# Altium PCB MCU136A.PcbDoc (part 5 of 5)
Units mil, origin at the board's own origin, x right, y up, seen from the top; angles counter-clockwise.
Board outline 3937.01 x 4724.41 mil, 4 copper layers (Top Layer, Signal Layer 1, Signal Layer 2, Bottom Layer), stack 60 mil thick; 390 components, 224 nets, 1130 pads, 1344 vias.
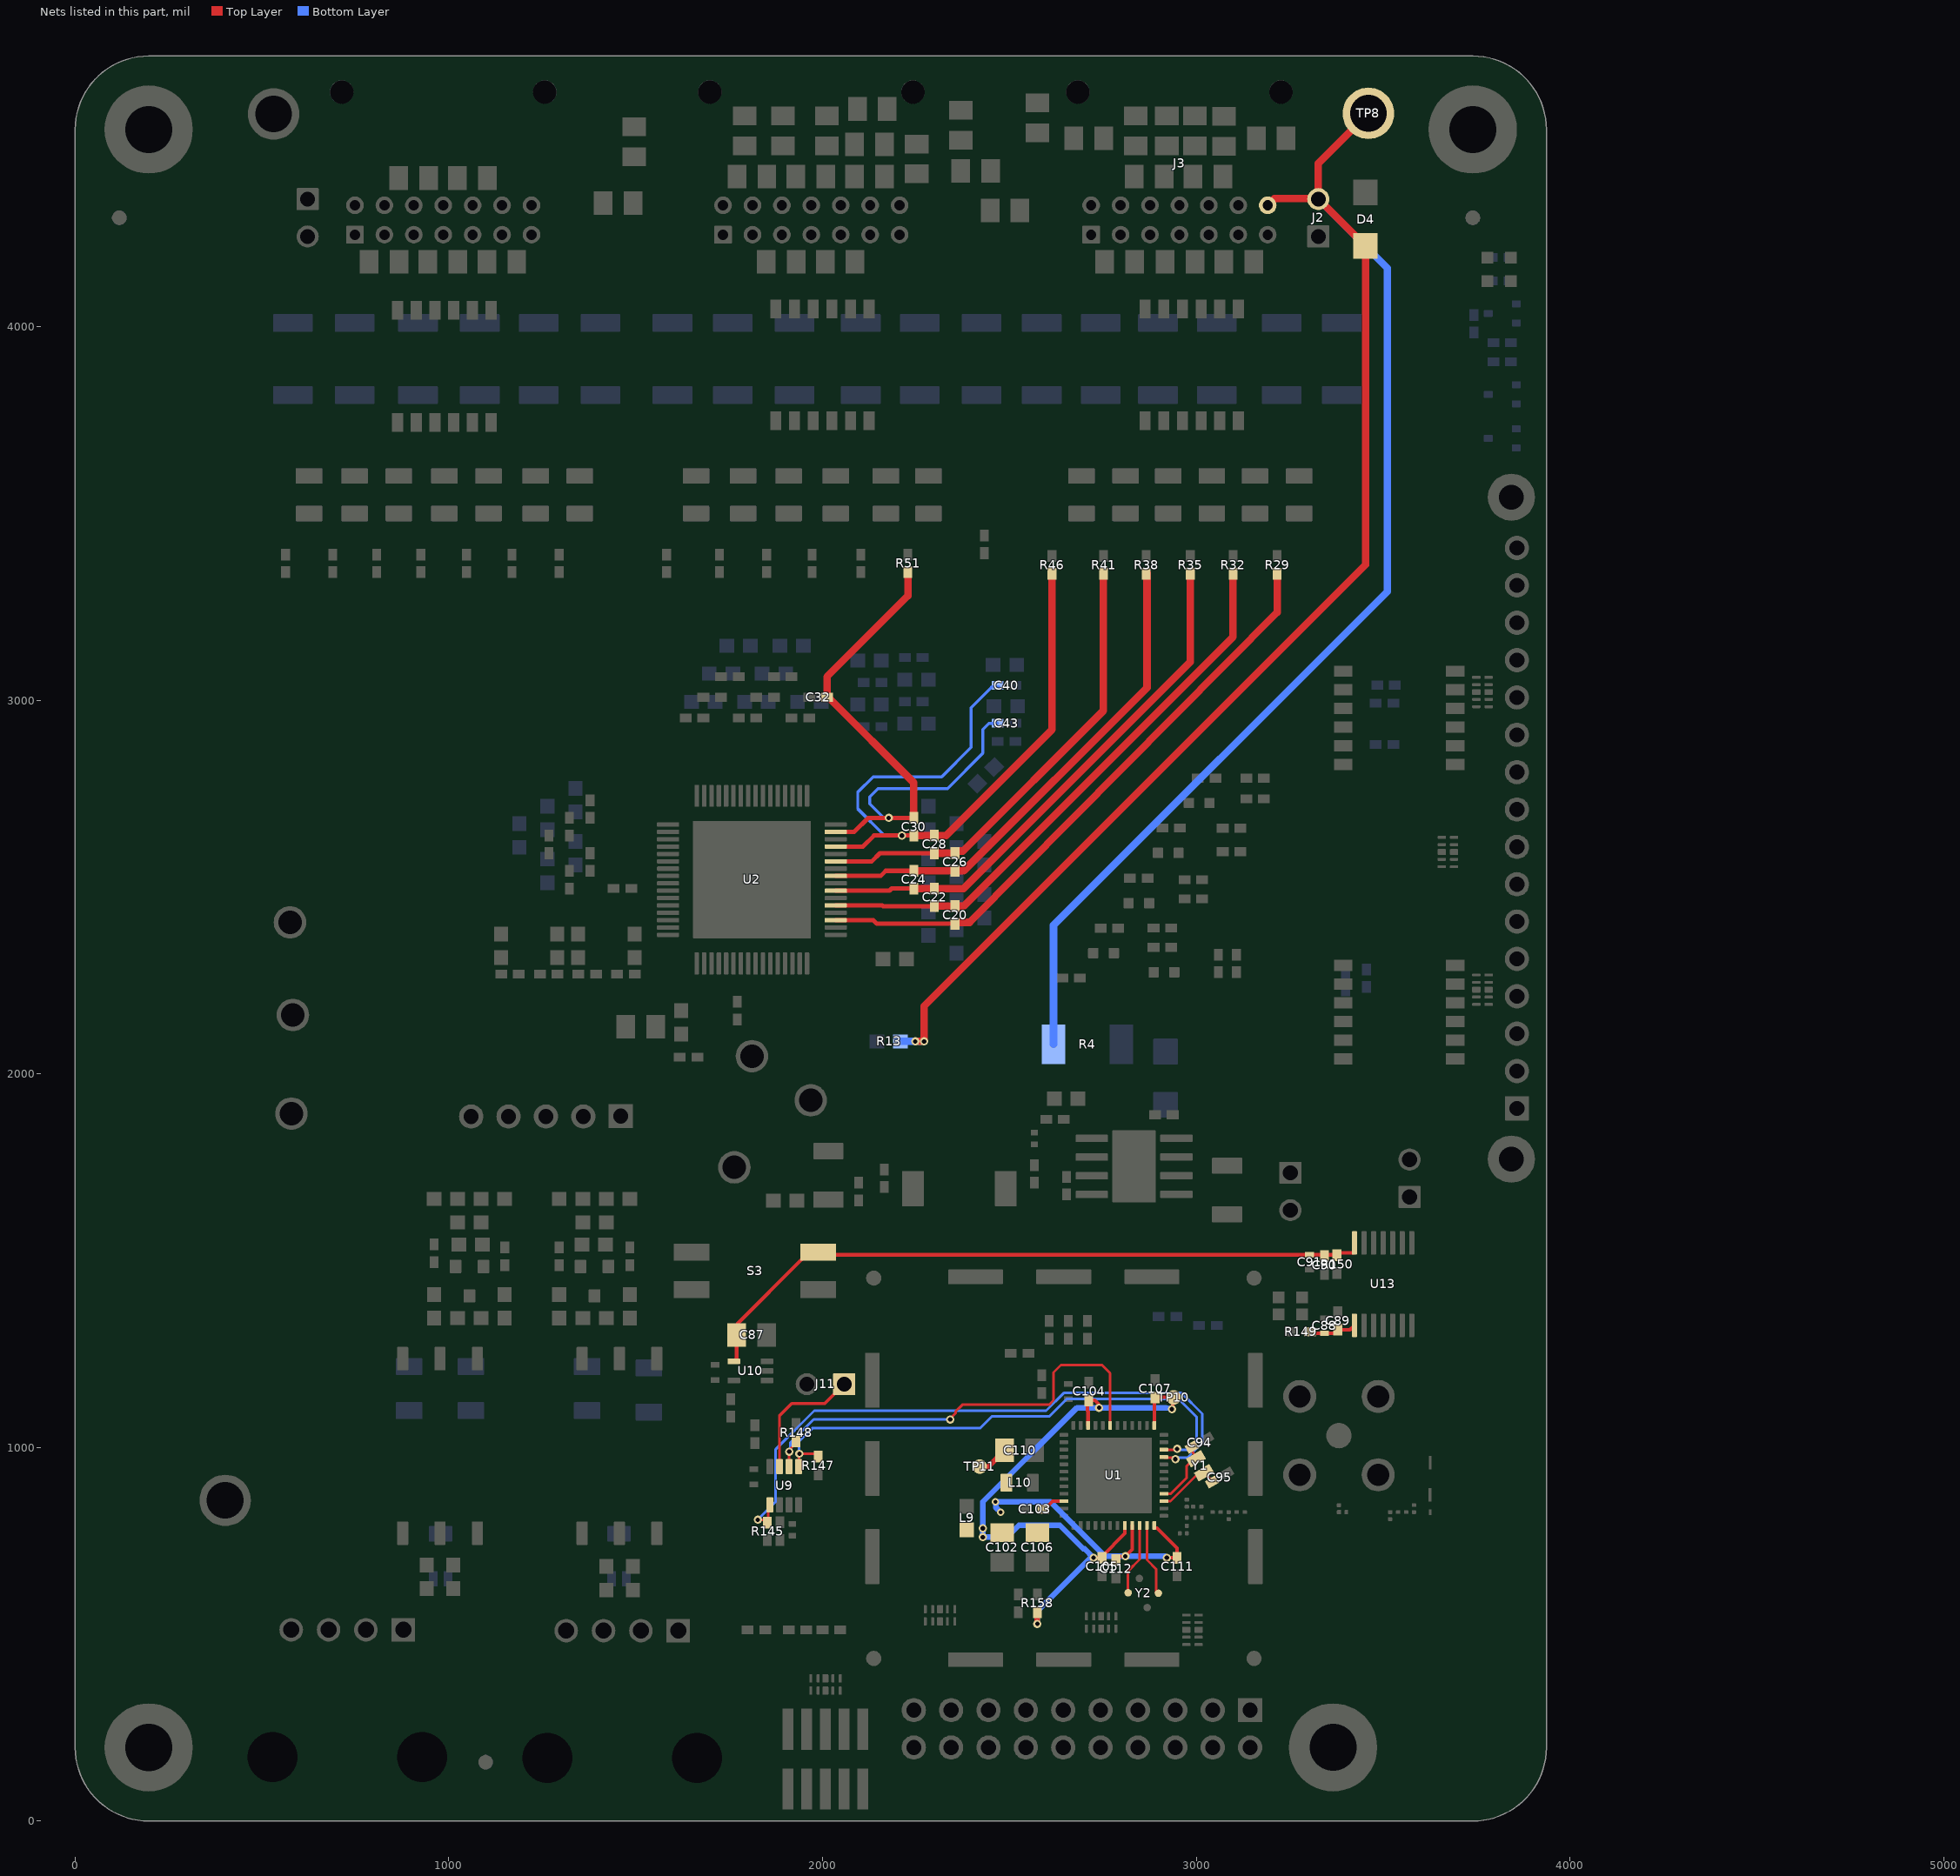
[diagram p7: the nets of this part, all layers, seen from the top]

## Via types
v1: diameter 22, hole 12, Top Layer to Bottom Layer, tented both sides, 890 vias
v2: diameter 22.01, hole 12.01, Top Layer to Bottom Layer, tented both sides, 402 vias
v3: diameter 19.68, hole 7.87, Top Layer to Bottom Layer, tented both sides, 21 vias
v4: diameter 24, hole 8, Top Layer to Bottom Layer, tented both sides, 12 vias
v5: diameter 20, hole 10, Top Layer to Bottom Layer, tented both sides, 7 vias
v6: diameter 24.8, hole 12.99, Top Layer to Bottom Layer, tented bottom, 6 vias
v7: diameter 17.46, hole 7.87, Top Layer to Bottom Layer, tented both sides, 6 vias

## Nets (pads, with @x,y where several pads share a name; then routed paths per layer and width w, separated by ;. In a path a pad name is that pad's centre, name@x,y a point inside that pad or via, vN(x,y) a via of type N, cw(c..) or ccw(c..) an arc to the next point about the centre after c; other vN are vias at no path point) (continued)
VC12: C30.2 C32.1 C43.1 R51.2 U2.15 | length 1616.1
  Top Layer w11.81: U2.15@2035.43,2647.64 2084.65,2647.64 2122.05,2685.04 v2(2177.17,2685.04) C30.2@2244.09,2685.04
  Top Layer w20: R51.2@2228.35,3342.52 2228.35,3279.53 2011.81,3062.99 C32.1@2011.81,3007.87 2013.62,3006.06 2017.56,3006.06 2244.09,2779.53 C30.2@2244.09,2685.04
  Bottom Layer w8: v2(2177.17,2685.04) 2163.55,2685.04 2125.98,2722.6 2125.98,2741.06 2148.7,2763.78 2334.65,2763.78 2429.13,2858.27 2429.13,2921.26 2445.44,2937.57 2467.9,2937.57 C43.1@2468.5,2938.17
VC13: C28.2 C30.1 C40.1 R46.2 U2.13 | length 1875.5
  Top Layer w11.81: U2.13@2035.43,2608.27 2108.27,2608.27 2137.8,2637.8 v2(2212.6,2637.8) C30.1@2240.16,2637.8
  Top Layer w20: C30.1@2244.09,2637.8 C28.2@2299.21,2637.8 2330.71,2637.8 2614.17,2921.26 R46.2@2614.17,3338.58 R46.2@2614.17,3342.52
  Bottom Layer w8: v2(2212.6,2637.8) 2165.81,2637.8 2094.33,2709.27 2094.33,2754.39 2135.21,2795.28 2318.9,2795.28 2397.64,2874.02 2397.64,2980.31 2448.53,3031.2 2452.76,3035.43 C40.1@2472.44,3035.43
VC14: C26.2 C28.1 R41.2 U2.11 | length 1248.2
  Top Layer w11.81: U2.11@2035.43,2568.9 2131.89,2568.9 2153.54,2590.55 C28.1@2299.21,2590.55
  Top Layer w20: C28.1@2299.21,2590.55 C26.2@2354.33,2590.55 2354.33,2594.49 2356.14,2596.3 2375.83,2596.3 2751.43,2971.9 2751.43,3334.1 R41.2@2751.97,3334.65
VC15: C24.2 C26.1 R38.2 U2.9 | length 1351.5
  Top Layer w11.81: U2.9@2035.43,2529.53 2155.51,2529.53 2169.29,2543.31 C24.2@2244.09,2543.31
  Top Layer w20: C24.2@2244.09,2543.31 C26.1@2354.33,2543.31 2377.95,2543.31 2868.32,3033.67 2868.32,3340.34 R38.2@2866.14,3342.52
VC16: C22.2 C24.1 R35.2 U2.7 | length 1438.6
  Top Layer w11.81: U2.7@2035.43,2490.16 2179.13,2490.16 2185.04,2496.06 C24.1@2244.09,2496.06
  Top Layer w20: C24.1@2244.09,2496.06 C22.2@2299.21,2496.06 2377.95,2496.06 2984.25,3102.36 R35.2@2984.25,3338.58
VC17: C20.2 C22.1 R32.2 U2.5 | length 1537.1
  Top Layer w11.81: U2.5@2035.43,2450.79 2159.45,2450.79 2161.42,2448.82 C22.1@2299.21,2448.82 ; R32.2@3098.43,3338.58 R32.2@3102.36,3342.52
  Top Layer w20: C22.1@2299.21,2448.82 2377.95,2448.82 3098.43,3169.29 R32.2@3098.43,3338.58
VC18: C20.1 R29.2 U2.3 | length 1634.2
  Top Layer w11.81: U2.3@2035.43,2411.42 2135.83,2411.42 2145.67,2401.57 C20.1@2354.33,2401.57
  Top Layer w20: C20.1@2354.33,2405.51 2393.7,2405.51 3216.54,3235.27 R29.2@3216.54,3338.58
VCCA: C88.1 C89.1 R149.1 U13.1 | length 129.9
  Top Layer w10: R149.1@3303.81,1309.42 3307.78,1305.45 3346.05,1305.45 3376.32,1305.45 3385.83,1314.96 3411.42,1314.96 U13.1@3423.23,1326.77
VDDR: C110.1 C111.1 C112.1 L10.2 TP11.1 U1.45 U1.48 | length 889.6
  Top Layer w9.45: C112.1@2785.28,698.72 2795.13,708.58 v2(2810.52,708.58) 2828.74,726.8 U1.45@2828.74,791.34 ; U1.48@2887.8,791.34 2887.8,784.45 2887.99,784.25 2894.88,784.25 2948.82,730.32 C111.1@2948.82,712.6 ; v2(2921.26,704.72) C111.1@2948.82,704.72
  Top Layer w15: TP11.1@2425.53,948.48 2443.91,948.48 C110.1@2487.56,992.13
  Bottom Layer w15: v5(2476.38,826.77) 2463.45,839.7 2463.45,853.5 v5(2462.49,854.45) 2610,854.45 2755.87,708.58 v2(2810.52,708.58) 2915.51,708.58 2919.36,704.72 v2(2921.26,704.72)
VDDS: C102.1 C103.1 C104.1 C105.1 C106.1 C107.1 L9.2 R158.2 TP10.1 U1.13 U1.22 U1.34 U1.44 | length 1769.7
  Top Layer w9.45: C103.1@2602.36,842.52 2616.14,856.3 U1.34@2645.67,856.3 ; U1.22@2710.63,1059.06 2710.63,1096.46 2708.66,1098.43 2708.66,1125.98 2729.11,1125.98 2737.75,1117.34 2737.75,1108.7 v2(2740.16,1106.3) ; v2(2725.23,704.57) 2747.87,704.57 C105.1@2748.03,704.72 2748.03,708.66 2809.06,769.69 U1.44@2809.06,791.34 ; U1.13@2887.8,1059.06 2887.8,1124.02 C107.1@2889.76,1125.98 ; C107.1@2889.73,1133.57 2890.02,1133.86 TP10.1@2939.4,1133.86 2937.19,1131.65 2937.19,1107.75 v1@2939.4,1105.54
  Top Layer w15: v1(2574.8,527.56) R158.2@2574.8,559.06
  Bottom Layer w15: v1(2574.8,527.56) 2574.8,562.21 2717.16,704.57 v2(2725.23,704.57) 2701.04,728.75 2697.65,728.75 2635.06,791.34 2525.76,791.34 2494.27,759.84 v2(2429.13,759.84) v2(2429.13,783.46) 2429.13,854.33 2681.1,1106.3 v2(2740.16,1106.3) 2919.37,1106.3 v1(2934.98,1102.5)
VPWR: D4.1 J2.2 J3.14 R4.2 R13.1 TP8.1 | length 6020.4
  Top Layer w19.68: v2(2248.03,2086.61) v2(2271.65,2086.61) 2271.65,2181.1 3452.76,3362.2 D4.1@3452.76,4215.94
  Top Layer w20: J3.14@3191.22,4324.8 3208.94,4342.52 J2.2@3326.77,4342.52 ; D4.1@3452.76,4215.94 3327.36,4341.34 J2.2@3326.77,4341.34 J2.2@3326.77,4342.52 ; TP8.1@3460.63,4570.87 3326.77,4437.01 J2.2@3326.77,4342.52
  Bottom Layer w19.68: R13.1@2208.66,2086.61 v2(2248.03,2086.61) v2(2271.65,2086.61)
  Bottom Layer w20: R4.2@2618.11,2078.74 2618.11,2397.64 3511.81,3291.34 3511.81,4156.3 J2.2@3326.77,4341.34
WD_SET0: R145.1 U1.9 U9.1 | length 1706.1
  Top Layer w7: v1(1826.99,806.49) 1847.06,806.49 R145.1@1854.33,799.21 ; R145.1@1854.33,807.09 U9.1@1854.33,841.54 ; U1.9@2913.39,974.41 2914.81,972.99 2935.61,972.99 2940.16,968.44 v1(2944.22,968.44)
  Bottom Layer w7: v1(1826.99,806.49) 1826.99,807.3 1874.84,855.15 1874.84,995.24 1978.02,1098.43 2598.43,1098.43 2645.67,1145.67 2960.63,1145.67 3016.08,1090.22 3016.08,1012.14 2976.38,972.44 2948.82,972.44 v1@2940.94,964.57
WD_SET1: R147.2 U1.10 U9.5 | length 1414.5
  Top Layer w7: U9.5@1936.02,948.82 1937.14,949.94 1937.14,981.88 v1(1938.26,983) 1986.94,983 R147.2@1989.62,980.32 ; U1.10@2913.39,994.09 v1@2946.73,994.09
  Bottom Layer w7: v1(1938.26,983) 1937.01,984.25 1937.01,1015.75 1972.44,1051.18 2421.26,1051.18 2452.76,1082.68 2606.3,1082.68 2653.54,1129.92 2952.76,1129.92 3001.28,1081.4 3001.28,1015.73 2978.75,993.19 2951.69,993.19 v1(2948.82,996.06)
WDI_CC: R148.2 U1.19 U9.6 | length 1232.3
  Top Layer w7: U9.6@1911.91,950.3 1910.64,951.56 1910.64,988.51 1913.72,991.59 1913.72,996.4 R148.2@1929.13,1011.81 ; v1(2341.78,1074.8) 2341.78,1076.98 2355.89,1091.1 2355.89,1096.05 2374.02,1114.17 2606.3,1114.17 2618.11,1125.98 2618.11,1200.79 2637.8,1220.47 2748.03,1220.47 2769.69,1198.82 U1.19@2769.69,1059.06
  Bottom Layer w7: v1@1913.39,988.72 1913.39,1011.81 1976.38,1074.8 v1(2341.78,1074.8)
  other v1: 1910.85,988.72
WDO_T: J11.1 U9.7 | length 344
  Top Layer w8: U9.7@1884.84,948.82 1884.84,1084.86 1917.32,1117.34 2005.92,1117.34 J11.1@2057.87,1169.29
WL_PWR: C87.2 C90.1 C91.1 R150.1 S3.4 U10.4 U13.14 | length 1835.9
  Top Layer w10: U10.4@1762.8,1230.31 1770.31,1237.83 C87.2@1770.31,1300.96 ; C87.2@1771.65,1300.96 1771.65,1330.71 1945.16,1504.21 1945.16,1505.2 1955.71,1515.75 R150.1@3376.13,1515.75 ; R150.1@3376.13,1514.05 3382.83,1520.75 3421.34,1520.75 U13.14@3423.23,1522.64
X32K_Q1: C95.1 U1.3 Y1.2 | length 166.7
  Top Layer w7: U1.3@2913.39,856.3 2931.1,856.3 3001.97,927.17 3015.99,927.17 Y1.2@3020.94,932.12
  Top Layer w8: Y1.2@3020.94,932.12 3039.24,913.83 C95.1@3039.24,911.97
X32K_Q2: C94.1 U1.4 Y1.1 | length 171.4
  Top Layer w7: U1.4@2913.39,876.39 2932.35,876.39 2973.91,917.95 2973.91,949.25 2994.29,969.63 Y1.1@2999.29,969.63 2999.29,977.01 2990.87,985.42 C94.1@2990.87,994.69
X48M_N: U1.46 Y2.1 | length 192.9
  Top Layer w7: Y2.1@2817.45,611.31 2817.45,669.33 2848.43,700.31 U1.46@2848.43,791.34
X48M_P: U1.47 Y2.3 | length 191.4
  Top Layer w7: U1.47@2868.11,791.34 2868.11,698.82 2893.32,673.61 Y2.3@2893.32,610.33
pads on no net: FID1.1 FID2.1 FID3.1 FID4.1 FID5.1 FID6.1 J3. J3.1 J4. J4.1 J4.14 J5. J5.14 J7.1 J7.2 J7.MH1 J7.MH2 J9.3 J9.4 J9.MH1 J9.MH2 J10.6 J10.7 J10.8 MP1. MP2. MP3. MP4. S1.2 S1.11 S3.3 SH-J1.0 SH-J2.0 SH-J3.0 SH-J4.0 SH-J5.0 T1.5 T2.5 U1.5 U1.6 U1.7 U1.8 U1.20 U1.21 U1.28 U1.29 U1.30 U1.31 U1.32 U1.36 U1.42 U1.43 U3.3@3657.15,2593.74 U3.8@3690.03,2593.74 U4.3@3749.52,2225.2 U4.8@3782.39,2225.2 U5.3@3749.52,3022 U5.8@3782.39,3022 U8.3@2007.87,348.96 U8.5 U8.6 U8.8@2007.87,381.83 U10.1 U10.3 U11.3@2745.65,515.06 U11.8@2745.65,547.93 U12.2 U12.3@3006.44,511.81 U12.4 U12.5 U12.6 U12.7 U12.8@2973.56,511.81 U12.9 U13.3 U13.6 U13.9 U13.12 U14.3@2314.5,534.18 U14.8@2314.5,567.06

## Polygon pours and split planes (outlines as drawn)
GND on Signal Layer 1 "SIGNAL_LAYER_1_GND_P092" (solid, pour order 92): 0,4724.41 3937.01,4724.41 3937.01,0 0,0
GND on Signal Layer 2 "SIGNAL_LAYER_2_GND_P093" (solid, pour order 93): 0,4724.41 3937.01,4724.41 3937.01,0 0,0
GND on Bottom Layer "BOTTOM_LAYER_GND_P096" (solid, remove dead copper, pour order 96): 3937.01,0 0,0 0,4724.41 3937.01,4724.41
GND on Top Layer "TOP_LAYER_GND_P094" (solid, remove dead copper, pour order 94): 3937.01,0 0,0 0,4724.41 3937.01,4724.41

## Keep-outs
Keep-Out Layer:
  text ".Layer_Name" at 446,-854.48 h60

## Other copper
Top Layer:
  pour cut-out: 3342.52,1070.87 cw(c3381.89,1031.5) 3421.26,1070.87 cw(c3381.89,1031.5) 3421.26,992.13 cw(c3381.89,1031.5) 3342.52,992.13 cw(c3381.89,1031.5)
  pour cut-out: 2078.44,305.8 2087.31,305.8 2087.31,184.68 2078.44,184.68 2078.44,305.79
  pour cut-out: 1928.44,302.64 1937.31,302.64 1937.31,184.68 1928.44,184.68
  pour cut-out: 2803.09,676.98 2806.01,674.05 2806.01,671.6 2838.74,704.32 2838.74,714.26 2835.81,714.26 2833.74,716.33 2827.52,710.12 2827.52,701.53 2817.56,691.57 2805.79,691.57 2803.09,688.87
  pour cut-out: 3662.31,3006.76 3662.31,2998.76 3709.54,2998.76 3712.93,3002.14 3712.93,3004.84 3711.01,3006.76
  region net LDO_C: 3023.62,1787.4 3023.62,1724.41 3039.37,1724.41 3043.31,1728.35 3043.31,1775.59
  pour cut-out: 2990.98,4105.27 2993.86,4105.27 2995.94,4103.2 2995.46,4102.72 2995.46,4078.73 2992.42,4078.73 2991.94,4078.25 2992.58,4077.61 2992.58,4016.38 2995.46,4016.38 2995.94,4016.86 2995.61,4017.18 2983.77,4017.18 2983.77,4078.08 2983.49,4078.36 2978.1,4078.36 2978.1,4091.11 2977.25,4091.96 2990.57,4105.27
  pour cut-out: 1987.83,4113.4 1989.01,4114.58 1993.88,4114.58 1993.88,4112.89 2008.01,4098.77 2007.51,4098.26 2007.51,4078.25 2004.31,4078.25 2003.81,4077.74 2004.14,4077.41 2004.14,4016.69 2008.52,4016.69 2008.68,4016.52 2008.13,4015.97 2008.13,3936.86 1984.99,3936.86 1984.45,3937.4 1989.35,3942.3 1989.35,4014.99 1991.26,4016.89 1991.8,4016.35 1996.43,4016.35 1996.43,4078.44 1996.11,4078.76 1995.84,4078.5 1988.21,4078.5 1988.21,4113.1 1988.05,4113.25
  pour cut-out: 2046.07,4077.95 2046.07,4016.68 2046.87,4015.88 2046.6,4015.61 2041.56,4015.61 2041.56,3929.94 2053.23,3918.27 2056.95,3918.27 2059.34,3920.66 2058.8,3921.19 2058.8,4017.21 2056.15,4017.21 2054.03,4019.33 2054.03,4077.95 2046.6,4077.95 2046.34,4077.68
  pour cut-out: 3321.28,3578.06 3321.28,3523.61 3321.02,3523.35 3316.82,3527.56 3232.28,3527.56 3232.28,3543.31 3267.72,3578.74 3321.46,3578.74
  pour cut-out: 2972.44,3645.67 2996.06,3645.67 2996.06,3582.68 2968.5,3555.12 2964.57,3555.12 2964.57,3531.5 2968.5,3527.56 2964.57,3523.62 2885.83,3523.62 2885.83,3535.43 2881.89,3539.37 2913.39,3570.87 2964.57,3570.87 2972.44,3578.74
  pour cut-out: 2657.48,3433.07 2629.92,3433.07 2629.92,3519.68 2681.1,3570.87 2736.22,3570.87 2740.16,3574.8 2740.16,3645.67 2763.78,3645.67 2763.78,3582.68 2736.22,3555.12 2736.22,3527.56 2653.54,3527.56 2645.67,3519.68 2645.67,3444.88
  pour cut-out: 2271.65,3570.87 2326.77,3570.87 2326.77,3523.62 2248.03,3523.62 2244.09,3527.56 2244.09,3543.31
  pour cut-out: 1952.76,3649.61 1992.13,3649.61 1988.19,3645.67 1988.19,3582.68 1956.69,3551.18 1956.69,3527.56 1866.14,3527.56 1866.14,3543.31 1870.08,3543.31 1897.64,3570.87 1948.82,3570.87 1956.69,3578.74 1952.76,3582.68
  pour cut-out: 1393.7,3570.87 1393.7,3527.56 1311.02,3527.56 1311.02,3543.31 1338.58,3570.87
  pour cut-out: 665.35,3657.48 708.66,3657.48 700.79,3649.61 700.79,3594.49 673.23,3566.93 673.23,3527.56 578.74,3527.56 578.74,3539.37 610.24,3570.87 665.35,3570.87 673.23,3578.74 669.29,3582.68 669.29,3653.54
  pour cut-out: 1023.62,3661.42 1070.87,3661.42 1070.87,3657.48 1059.06,3645.67 1059.06,3594.49 1031.5,3566.93 1031.5,3527.56 948.82,3527.56 948.82,3531.5 992.13,3574.8 1031.5,3574.8 1031.5,3578.74 1035.43,3582.68 1035.43,3649.61
  region net CB13: 2661.42,3440.94 2653.54,3452.76 2653.54,3519.68 2732.28,3519.68 2732.28,3452.76 2724.41,3440.94
  region net CELL13: 2724.41,3657.48 2732.28,3645.67 2732.28,3578.74 2653.54,3578.74 2653.54,3645.67 2661.42,3657.48
  region net CB18: 3244.09,3440.94 3236.22,3452.76 3236.22,3519.68 3314.96,3519.68 3314.96,3452.76 3307.09,3440.94
  region net CB17: 3125.98,3440.94 3118.11,3452.76 3118.11,3519.68 3196.85,3519.68 3196.85,3452.76 3188.98,3440.94
  region net CB16: 3010.15,3441.45 3002.27,3453.26 3002.27,3520.19 3081.01,3520.19 3081.01,3453.26 3073.14,3441.45
  region net CB15: 2893.7,3440.94 2885.83,3452.76 2885.83,3519.68 2964.57,3519.68 2964.57,3452.76 2956.69,3440.94
  region net CB14: 2779.53,3440.94 2771.65,3452.76 2771.65,3519.68 2850.39,3519.68 2850.39,3452.76 2842.52,3440.94
  region net CELL18: 3307.09,3657.48 3314.96,3645.67 3314.96,3578.74 3236.22,3578.74 3236.22,3645.67 3244.09,3657.48
  region net CELL17: 3188.98,3657.48 3196.85,3645.67 3196.85,3578.74 3118.11,3578.74 3118.11,3645.67 3125.98,3657.48
  region net CELL16: 3072.95,3657.19 3080.82,3645.37 3080.82,3578.45 3002.08,3578.45 3002.08,3645.37 3009.95,3657.19
  region net CELL15: 2956.69,3657.48 2964.57,3645.67 2964.57,3578.74 2885.83,3578.74 2885.83,3645.67 2893.7,3657.48
  region net CELL14: 2842.52,3657.48 2850.39,3645.67 2850.39,3578.74 2771.65,3578.74 2771.65,3645.67 2779.53,3657.48
  region net CELL12: 2314.96,3657.48 2322.83,3645.67 2322.83,3578.74 2244.09,3578.74 2244.09,3645.67 2251.97,3657.48
  region net CELL11: 2200.79,3657.48 2208.66,3645.67 2208.66,3578.74 2129.92,3578.74 2129.92,3645.67 2137.8,3657.48
  region net CELL10: 2066.93,3657.48 2074.8,3645.67 2074.8,3578.74 1996.06,3578.74 1996.06,3645.67 2003.94,3657.48
  region net CELL9: 1940.94,3657.48 1948.82,3645.67 1948.82,3578.74 1870.08,3578.74 1870.08,3645.67 1877.95,3657.48
  region net CELL8: 1818.9,3657.48 1826.77,3645.67 1826.77,3578.74 1748.03,3578.74 1748.03,3645.67 1755.91,3657.48
  region net CELL7: 1692.91,3657.48 1700.79,3645.67 1700.79,3578.74 1622.05,3578.74 1622.05,3645.67 1629.92,3657.48
  region net CELL6: 1381.89,3657.48 1389.76,3645.67 1389.76,3578.74 1311.02,3578.74 1311.02,3645.67 1318.9,3657.48
  region net CELL5: 1263.78,3657.48 1271.65,3645.67 1271.65,3578.74 1192.91,3578.74 1192.91,3645.67 1200.79,3657.48
  region net CELL4: 1137.8,3657.48 1145.67,3645.67 1145.67,3578.74 1066.93,3578.74 1066.93,3645.67 1074.8,3657.48
  region net CELL3: 1019.68,3657.48 1027.56,3645.67 1027.56,3578.74 948.82,3578.74 948.82,3645.67 956.69,3657.48
  region net CELL2: 897.64,3657.48 905.51,3645.67 905.51,3578.74 826.77,3578.74 826.77,3645.67 834.65,3657.48
  region net CELL1: 779.53,3657.48 787.4,3645.67 787.4,3578.74 708.66,3578.74 708.66,3645.67 716.54,3657.48
  region net CELL0: 657.48,3657.48 665.35,3645.67 665.35,3578.74 586.61,3578.74 586.61,3645.67 594.49,3657.48
  region net CB12: 2251.97,3440.94 2244.09,3452.76 2244.09,3519.68 2322.83,3519.68 2322.83,3452.76 2314.96,3440.94
  region net CB11: 2137.8,3440.94 2129.92,3452.76 2129.92,3519.68 2208.66,3519.68 2208.66,3452.76 2200.79,3440.94
  region net CB10: 2003.94,3440.94 1996.06,3452.76 1996.06,3519.68 2074.8,3519.68 2074.8,3452.76 2066.93,3440.94
  region net CB9: 1877.95,3440.94 1870.08,3452.76 1870.08,3519.68 1948.82,3519.68 1948.82,3452.76 1940.94,3440.94
  region net CB8: 1755.91,3440.94 1748.03,3452.76 1748.03,3519.68 1826.77,3519.68 1826.77,3452.76 1818.9,3440.94
  region net CB7: 1629.92,3440.94 1622.05,3452.76 1622.05,3519.68 1700.79,3519.68 1700.79,3452.76 1692.91,3440.94
  region net CB6: 1318.9,3440.94 1311.02,3452.76 1311.02,3519.68 1389.76,3519.68 1389.76,3452.76 1381.89,3440.94
  region net CB5: 1200.79,3440.94 1192.91,3452.76 1192.91,3519.68 1271.65,3519.68 1271.65,3452.76 1263.78,3440.94
  region net CB4: 1074.8,3440.94 1066.93,3452.76 1066.93,3519.68 1145.67,3519.68 1145.67,3452.76 1137.8,3440.94
  region net CB3: 956.69,3440.94 948.82,3452.76 948.82,3519.68 1027.56,3519.68 1027.56,3452.76 1019.68,3440.94
  region net CB2: 834.65,3440.94 826.77,3452.76 826.77,3519.68 905.51,3519.68 905.51,3452.76 897.64,3440.94
  region net CB1: 716.54,3440.94 708.66,3452.76 708.66,3519.68 787.4,3519.68 787.4,3452.76 779.53,3440.94
  region net CB0: 594.49,3440.94 586.61,3452.76 586.61,3519.68 665.35,3519.68 665.35,3452.76 657.48,3440.94
  region net GND: 3610.27,990.43 3622.08,990.43 3622.08,933.6 3610.27,933.6
  region net GND: 3622.05,900.47 3622.05,845.35 3610.24,845.35 3610.24,900.47
  pour cut-out: 946.85,1318.9 946.85,1614.17 986.22,1708.66 1446.85,1708.66 1498.03,1614.17 1498.03,1318.9
  region net VDDR: 2511.81,1019.68 2511.81,874.02 2488.19,850.39 2488.19,822.83 2480.32,814.96 2460.63,814.96 2444.88,830.71 2444.88,1000 2464.57,1019.68
  pour cut-out: 1767.5,2319.86 1798.99,2319.86 1798.99,2330.71 1767.5,2330.71
  region net GND: 1637.8,2696.85 1637.8,2350.39 1984.25,2350.39 1984.25,2696.85
  pour cut-out: 1775.59,2129.92 1791.34,2129.92 1807.09,2145.67 1807.09,2177.17 1775.59,2177.17
  region net GND: 2543.31,716.54 2543.31,645.67 2551.18,637.8 2598.43,637.8 2606.3,645.67 2606.3,716.54
  region net GND: 2543.31,960.63 2618.11,960.63 2622.05,964.57 2622.05,976.38 2614.17,984.25 2598.43,984.25 2590.55,992.13 2543.31,992.13 2543.31,972.44
  region net 3V3_CC: 2403.54,822.83 2403.54,862.2 2336.61,862.2 2328.74,854.33 2328.74,842.52 2336.61,834.65 2360.24,834.65 2364.17,830.71 2364.17,822.83
  region net GND: 2448.82,716.54 2448.82,645.67 2456.69,637.8 2503.94,637.8 2511.81,645.67 2511.81,716.54
  region net VDDS: 2366.14,759.84 2381.89,744.09 2606.3,744.09 2606.3,846.46 2574.8,846.46 2574.8,811.02 2562.99,799.21 2433.07,799.21 2366.14,799.21
  region net DCDC_SW: 2622.05,874.02 2574.8,874.02 2574.8,937.01 2594.49,937.01 2625.98,877.95
  text ".Layer_Name" at 446,-854.48 h60
Signal Layer 1:
  pour cut-out: 3342.52,1070.87 cw(c3381.89,1031.5) 3421.26,1070.87 cw(c3381.89,1031.5) 3421.26,992.13 cw(c3381.89,1031.5) 3342.52,992.13 cw(c3381.89,1031.5)
Bottom Layer:
  region net CB6: 1311.02,3520.59 1389.76,3520.59 1389.76,3452.76 1385.83,3446.85 1381.89,3440.94 1318.9,3440.94 1311.02,3448.82 1311.02,3452.76
  region net CB18: 3244.09,3440.94 3236.22,3452.76 3236.22,3519.69 3314.96,3519.69 3314.96,3452.76 3307.09,3440.94
  region net CELL0: 657.48,3657.48 665.35,3645.67 665.35,3578.74 586.61,3578.74 586.61,3645.67 594.49,3657.48
  region net CB2: 834.65,3440.94 826.77,3452.76 826.77,3519.68 905.51,3519.68 905.51,3452.76 897.64,3440.94
  region net CB5: 1200.54,3441.76 1192.67,3453.57 1192.67,3520.5 1271.41,3520.5 1271.41,3453.57 1263.53,3441.76
  region net CELL8: 1818.9,3657.48 1826.77,3645.67 1826.77,3578.74 1748.03,3578.74 1748.03,3645.67 1755.91,3657.48
  region net CELL11: 2200.95,3657.54 2208.82,3645.73 2208.82,3578.8 2130.08,3578.8 2130.08,3645.73 2137.96,3657.54
  region net CELL10: 2067.1,3657.72 2074.98,3645.91 2074.98,3578.98 1996.24,3578.98 1996.24,3645.91 2004.11,3657.72
  region net CELL13: 2724.41,3657.48 2732.28,3645.67 2732.28,3578.74 2653.54,3578.74 2653.54,3645.67 2661.42,3657.48
  region net CELL15: 2956.84,3658 2964.71,3646.18 2964.71,3579.25 2885.97,3579.25 2885.97,3646.18 2893.85,3658
  region net CELL12: 2314.85,3657.15 2322.72,3645.34 2322.72,3578.41 2243.98,3578.41 2243.98,3645.34 2251.86,3657.15
  region net CELL9: 1940.66,3657.7 1948.53,3645.89 1948.53,3578.96 1869.79,3578.96 1869.79,3645.89 1877.67,3657.7
  region net CELL16: 3072.6,3657.1 3080.48,3645.29 3080.48,3578.36 3001.74,3578.36 3001.74,3645.29 3009.61,3657.1
  region net CELL14: 2842.52,3657.48 2850.39,3645.67 2850.39,3578.74 2771.65,3578.74 2771.65,3645.67 2779.53,3657.48
  region net CELL17: 3188.55,3657.07 3196.43,3645.25 3196.43,3578.33 3117.69,3578.33 3117.69,3645.25 3125.56,3657.07
  region net CELL18: 3307.09,3657.48 3314.96,3645.67 3314.96,3578.74 3236.22,3578.74 3236.22,3645.67 3244.09,3657.48
  region net CB7: 1630.43,3440.71 1622.56,3452.52 1622.56,3519.45 1701.3,3519.45 1701.3,3452.52 1693.42,3440.71
  region net CB11: 2137.49,3441 2129.62,3452.81 2129.62,3519.74 2208.36,3519.74 2208.36,3452.81 2200.48,3441
  region net CB16: 3010.18,3440.81 3002.31,3452.63 3002.31,3519.55 3081.05,3519.55 3081.05,3452.63 3073.17,3440.81
  region net CB15: 2893.96,3441.19 2886.09,3453 2886.09,3519.93 2964.83,3519.93 2964.83,3453 2956.95,3441.19
  region net CB17: 3125.98,3440.94 3118.11,3452.76 3118.11,3519.69 3196.85,3519.69 3196.85,3452.76 3188.98,3440.94
  region net CB14: 2779.47,3440.69 2771.6,3452.5 2771.6,3519.43 2850.34,3519.43 2850.34,3452.5 2842.46,3440.69
  region net CB13: 2660.57,3441.55 2652.69,3453.36 2652.69,3520.29 2731.43,3520.29 2731.43,3453.36 2723.56,3441.55
  region net CB8: 1755.8,3441.45 1747.92,3453.26 1747.92,3520.19 1826.66,3520.19 1826.66,3453.26 1818.79,3441.45
  region net CB9: 1878.07,3440.92 1870.2,3452.73 1870.2,3519.66 1948.94,3519.66 1948.94,3452.73 1941.06,3440.92
  region net CB10: 2003.86,3441.36 1995.98,3453.17 1995.98,3520.1 2074.72,3520.1 2074.72,3453.17 2066.85,3441.36
  region net CB12: 2251.97,3440.94 2244.09,3452.76 2244.09,3519.69 2322.83,3519.69 2322.83,3452.76 2314.96,3440.94
  region net CELL4: 1137.55,3657.63 1145.43,3645.82 1145.43,3578.89 1066.69,3578.89 1066.69,3645.82 1074.56,3657.63
  region net CELL5: 1263.78,3657.48 1271.65,3645.67 1271.65,3578.74 1192.91,3578.74 1192.91,3645.67 1200.79,3657.48
  region net CELL3: 1019.69,3657.48 1027.56,3645.67 1027.56,3578.74 948.82,3578.74 948.82,3645.67 956.69,3657.48
  region net CELL1: 779.41,3657.02 787.28,3645.21 787.28,3578.28 708.54,3578.28 708.54,3645.21 716.42,3657.02
  region net CELL7: 1692.91,3657.48 1700.79,3645.67 1700.79,3578.74 1622.05,3578.74 1622.05,3645.67 1629.92,3657.48
  region net CB1: 716.54,3440.94 708.66,3452.76 708.66,3519.68 787.4,3519.68 787.4,3452.76 779.53,3440.94
  region net CB3: 956.28,3440.73 948.4,3452.54 948.4,3519.47 1027.14,3519.47 1027.14,3452.54 1019.27,3440.73
  region net CB4: 1074.8,3440.94 1066.93,3452.76 1066.93,3519.69 1145.67,3519.69 1145.67,3452.76 1137.8,3440.94
  region net CB0: 594.49,3442.91 586.61,3454.72 586.61,3521.65 665.35,3521.65 665.35,3454.72 657.48,3442.91
  region net CELL2: 897.64,3657.48 905.51,3645.67 905.51,3578.74 826.77,3578.74 826.77,3645.67 834.65,3657.48
  region net CELL6: 1381.89,3659.45 1389.76,3647.64 1389.76,3580.71 1311.02,3580.71 1311.02,3647.64 1318.9,3659.45
  text ".Layer_Name" at 446,-854.48 h60
Multi-Layer:
  pour cut-out: 1767.72,0 1767.72,708.66 1688.98,787.4 1688.98,1082.68 1688.98,1295.28 1665.35,1318.9 862.2,1318.9 732.28,1318.9 732.28,912.46 389.76,509.5 389.76,0
  pour cut-out: 3622.05,0 3937.01,0 3937.01,1692.91 3622.05,1692.91 3622.05,807.09

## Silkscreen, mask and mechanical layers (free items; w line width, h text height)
Top Overlay:
  lines w6: 3311.02,2330.74 3311.02,2309.84 3330.51,2290.35 3351.21,2290.35
  lines w10: 834.65,1736.22 897.64,1736.22 909.45,1724.41 925.2,1724.41 956.69,1724.41 ; 1122.41,2238.08 1102.36,2212.6 1090.55,2212.6 ; 1374.02,2405.51 1350.39,2429.13 1153.54,2429.13 ; 1822.83,3047.24 1822.83,3094.49 ; 3315.45,1357.45 3325.56,1362.2 3344.75,1381.4 ; 3385.83,1285.86 3385.83,1236.22 3393.5,1230.16 ; 3728.35,1948.82 3740.16,1948.82 3795.28,2003.94 ; 594.12,1409.45 594.12,1736.01 ; 594.12,1409.45 334.27,1409.45 334.27,1736.01 594.12,1736.01 ; 594.12,1409.45 853.96,1409.45 853.96,1736.01 594.12,1736.01 ; 1090.55,2212.6 846.46,2212.6 846.46,2385.83 1090.55,2385.83 1090.55,2212.6 ; 1153.54,2429.13 1154.22,2612.3 910.13,2612.3 909.45,2429.13 1153.54,2429.13 ; 921.26,1303.15 921.26,1724.41 1527.56,1724.41 1527.56,1303.15 921.26,1303.15
  lines w22: 2209.86,16.46 2986.3,16.17
  text "VPWR" at 3372.2,4667.48 h40
  text "GND" at 470.93,4657.96 h40
  text "RL+" at 3295.68,4164.13 h60 r270
  text "RL-" at 578,4163.23 h60 r270
  text "VPWR" at 3440.35,3832.52 h40 r270
  text "CH_BB" at 2417.49,3761.65 h40 r270
  text "CELL18" at 3273.78,3419.13 h40 r270
  text "GND" at 3708.79,3393.83 h30
  text "CELL7" at 1580.87,3304.96 h40 r270
  text "CELL8" at 1706.85,3304.96 h40 r270
  text "CELL0" at 545.43,3301.02 h40 r270
  text "CELL1" at 667.48,3301.02 h40 r270
  text "CELL9" at 1860.39,3298.9 h40 r270
  text "CELL10" at 1958.66,3298.9 h40 r270
  text "CELL2" at 789.53,3297.09 h40 r270
  text "CELL11" at 2088.74,3297.09 h40 r270
  text "TSREF" at 3653.67,3295.4 h30
  text "CELL6" at 1289.53,3293.15 h40 r270
  text "CELL12" at 2226.54,3293.15 h40 r270
  text "CELL13" at 2592.46,3291.13 h40 r270
  text "CELL5" at 1155.67,3289.21 h40 r270
  text "CELL14" at 2734.41,3289.21 h40 r270
  text "CELL3" at 907.64,3285.28 h40 r270
  text "CELL4" at 1029.68,3285.28 h40 r270
  text "CELL15" at 2851.1,3285.4 h40 r270
  text "CELL16" at 2962.08,3284.5 h40 r270
  text "0" at 3767.84,3193.04 h30
  text "DANGER! / HIGH VOLTAGE" at 3644.05,3169.29 h60 r90
  text "1" at 3775.72,3094.61 h30
  text "PU10k| IO0" at 3055.12,3059.06 h30
  text "Rev. .pcb_rev" at 403.39,3024.72 h60 r90
  text "W_F | IO2" at 3083.5,2963.75 h30
  text "BQ79718V-Q1" at 2176.42,2936.26 h60
  text "L_R | IO2" at 3082.2,2911.64 h30
  text "3" at 3771.78,2893.83 h30
  text "T2 | IO3" at 3108.36,2864.27 h30
  text "Battery Monitor" at 2062.24,2853.89 h60
  text "T1 | IO4" at 3115.48,2813.48 h30
  text "4" at 3771.78,2791.46 h30
  text "5" at 3771.78,2693.04 h30
  text "MCU136" at 403.39,2595.25 h60 r90
  text "6" at 3771.78,2594.61 h30
  text "7" at 3771.78,2492.25 h30
  text "8" at 3771.78,2389.89 h30
  text "DVDD" at 330.71,2354.33 h40
  text "B | TSREF" at 3194.98,2342.68 h30
  text "TI WBMS - CC2662RQ1-CSU-EVM" at 377.95,2338.58 h70 r90
  text "9" at 3771.78,2291.46 h30
  text "T5 | IO9" at 3141.28,2222.81 h30
  text "T4 | IO10" at 3114.09,2178.11 h30
  text "T3 | IO11" at 3127.88,2129.3 h30
  text "AVDD" at 326.77,2122.05 h40
  text "CC2662-Q1" at 2432.32,2113.43 h60
  text "11" at 3752.09,2094.61 h30
  text "REF_CAP" at 1838.58,2094.49 h40
  text "L_G | DVDD" at 3076.87,2077.93 h30
  text "WBMS MCU" at 2450.38,2028.78 h60
  text "L_E | AVDD" at 3077.5,2025.79 h30
  text "LP" at 1071.74,1951.88 h30 r90
  text "LN" at 1170.17,1951.88 h30 r90
  text "G" at 1268.59,1951.88 h30 r90
  text "HN" at 1374.89,1951.88 h30 r90
  text "HP" at 1473.31,1951.88 h30 r90
  text "TSREF" at 2019.68,1944.88 h40
  text "AVDD" at 3602.49,1937.13 h30
  text "BAT" at 358.27,1881.89 h40
  text "GND" at 3696.98,1870.2 h30
  text "LDOIN" at 1622.05,1814.96 h40
  text "LED_R" at 3658.46,1702.06 h30 r90
  text "LED_G" at 3345.11,1641.41 h30 r90
  text "RST" at 1988.32,1232.41 h30
  text "VDDS" at 2954.18,1173.84 h30 r45
  text "VDDR" at 2432.39,981.98 h30 r90
  text "GND" at 342.52,677.17 h40
  text "COMH-" at 1325.69,573.06 h30 r90
  text "COMH+" at 1611.11,573.06 h30 r90
  text "COML+" at 846.73,566.06 h30 r90
  text "COML-" at 1127.61,566.06 h30 r90
  text "3V3" at 3103.04,58.84 h30 r45
  text "nCS" at 2610.24,54.62 h30 r45
  text "ISCL" at 2499.59,51.51 h30 r45
  text "ISDA" at 2401.57,46.75 h30 r45
  text "MOSI" at 2700.79,42.81 h30 r45
  text "MISO" at 2799.21,42.81 h30 r45
  text "IO28" at 2988.19,42.81 h30 r45
  text "UTXD" at 2212.6,38.87 h30 r45
  text "URXD" at 2311.02,38.87 h30 r45
  text "SCLK" at 2885.87,34.93 h30 r45
  text "3V3" at 3106.43,11.94 h30
  text "GND" at 3010.1,9.91 h30
  text ".Layer_Name" at 446,-854.48 h47.24
Bottom Overlay:
  lines w10: 2397.64,2519.68 2531.5,2519.68
  text "GND" at 447.01,3931.26 h40 r270
  text "COML+" at 758.03,258.03 h40 r270
  text "COML-" at 856.46,258.03 h40 r270
  text "COMH-" at 1289.53,258.03 h40 r270
  text "COMH+" at 1395.83,258.03 h40 r270
  text ".Layer_Name" at 446,-854.48 h47.24
Top Paste:
  text ".Layer_Name" at 446,-854.48 h60
Bottom Paste:
  text ".Layer_Name" at 446,-854.48 h60
Top Solder:
  region: 3366.14,314.96 cw(c3366.14,196.85) 3484.25,196.85 cw(c3366.14,196.85) 3366.14,78.74 cw(c3366.14,196.85) 3248.03,196.85 cw(c3366.14,196.85)
  text ".Layer_Name" at 446,-854.48 h60
  text ".Layer_Name" at 446,-854.48 h60
Bottom Solder:
  region: 3366.14,318.9 ccw(c3366.14,200.79) 3248.03,200.79 ccw(c3366.14,200.79) 3366.14,82.68 ccw(c3366.14,200.79) 3484.25,200.79 ccw(c3366.14,200.79)
  text ".Layer_Name" at 446,-854.48 h60
Drill Guide:
  text ".Layer_Name" at 446,-854.48 h60
M1 Board Outline:
  the board outline again, w3.94
  text ".Layer_Name" at 446,-854.48 h60
M2 Board Dimensions:
  rectangle: -6,-395.98 369,-270.98
  rectangle: -131,-270.98 -6,-145.98
  lines w7: -131,-270.98 869,-270.98 ; -131,-145.98 -131,-395.98 869,-395.98 869,-145.98 ; -131,-145 869,-145 ; -6,-395.98 -6,-145.98 ; 119,-395.98 119,-145.98 ; 369,-395.98 369,-145.98 ; 619,-395.98 619,-145.98
  lines w10: -1.76,4777.4 -1.76,4797.4 ; 58.24,4767.4 -1.76,4787.4 ; 58.24,4807.4 -1.76,4787.4 ; 1570.87,4787.4 -1.76,4787.4 ; 2362.62,4787.4 3935.25,4787.4 ; 3875.25,4767.4 3935.25,4787.4 ; 3875.25,4807.4 3935.25,4787.4 ; 3935.25,4777.4 3935.25,4797.4 ; 3956.69,57.01 3976.69,-2.99 ; 3956.69,4661.42 3976.69,4721.42 ; 3966.69,-2.99 3986.69,-2.99 ; 3966.69,4721.42 3986.69,4721.42 ; 3976.69,1963.34 3976.69,-2.99 ; 3976.69,2755.09 3976.69,4721.42 ; 3996.69,57.01 3976.69,-2.99 ; 3996.69,4661.42 3976.69,4721.42
  text "3937.008 (mil)" at 1580.87,4751.41 h60
  text "4724.409 (mil)" at 4012.68,1973.34 h60 r90
  text ".Layer_Name" at 446,-854.48 h60
M3 3D STEP Top:
  text ".Layer_Name" at 446,-854.48 h60
M4 3D STEP Bottom:
  text ".Layer_Name" at 446,-854.48 h60
M5 Assembly Top:
  lines w10: -423,-926.15 6177,-926.15 ; -423,-722.82 6179,-722.82 ; -423,-519.48 -423,-1129.48 3582,-1129.48 6179,-1129.48 6179,-519.48 -422.5,-519.48 -422.5,-1129.48 1153,-1129.48 ; 2042,-1129.48 2042,-519.48 ; 3309,-722.82 3309,-519.48 ; 4149,-722.82 4149,-519.48 ; 4771,-1135.98 4771,-933.15
  text "COMPONENTS MARKED 'DNP' SHOULD NOT BE POPULATED." at 1022.5,-314.48 h60
  text "ASSEMBLY VARIANT:" at 1022,-429.98 h60
  text ".VariantName" at 2058,-429.98 h60
  text "PCB VIEWED FROM TOP SIDE" at -359.5,-651.65 h60
  text "BOARD #:" at 2117,-651.65 h60
  text ".PRJ_Number" at 2662.5,-651.65 h60
  text "REV:" at 3507,-651.65 h60
  text ".PCB_Rev" at 3798.5,-651.65 h60
  text "SVN REV:" at 4345,-651.65 h60
  text ".VersionControl_RevNumber" at 4851,-651.65 h60
  text "TID #:" at 2117,-854.98 h60
  text ".TID" at 2662.5,-854.98 h60
  text "PLOT NAME =" at -359.5,-1060.32 h60
  text ".plot_File_Name" at 446,-1060.32 h60
  text "GENERATED    :" at 2119,-1060.32 h60
  text ".Print_Date" at 2988.5,-1060.32 h60
  text ".Print_Time" at 3717.5,-1060.32 h60
  text "TEXAS INSTRUMENTS" at 4982,-1060.32 h60
M6 Assembly Bottom:
  lines w10: -423.5,-723.32 6178.5,-723.32 ; -421.5,-926.65 6178.5,-926.65 ; 984.5,-1136.48 984.5,-933.65 ; 1606.5,-723.32 1606.5,-519.98 ; 2446.5,-723.32 2446.5,-519.98 ; 3713.5,-1129.98 3713.5,-519.98 ; 4602.5,-1129.98 6178,-1129.98 6178,-519.98 -423.5,-519.98 -423.5,-1129.98 2173.5,-1129.98 6178.5,-1129.98 6178.5,-519.98
  text "COMPONENTS MARKED 'DNP' SHOULD NOT BE POPULATED." at 5971,-313.98 h60
  text ".VariantName" at 4927,-429.98 h60
  text "ASSEMBLY VARIANT:" at 5966,-429.98 h60
  text ".VersionControl_RevNumber" at 904.5,-652.15 h60
  text "SVN REV:" at 1410.5,-652.15 h60
  text ".PCB_Rev" at 1957,-652.15 h60
  text "REV:" at 2248.5,-652.15 h60
  text ".PRJ_Number" at 3093,-652.15 h60
  text "BOARD #:" at 3638.5,-652.15 h60
  text "PCB VIEWED FROM BOTTOM SIDE" at 6115,-652.15 h60
  text ".TID" at 3093,-855.48 h60
  text "TID #:" at 3638.5,-855.48 h60
  text "TEXAS INSTRUMENTS" at 773.5,-1060.82 h60
  text ".Print_Time" at 2038,-1060.82 h60
  text ".Print_Date" at 2767,-1060.82 h60
  text "GENERATED    :" at 3636.5,-1060.82 h60
  text ".plot_File_Name" at 5309.5,-1060.82 h60
  text "PLOT NAME =" at 6115,-1060.82 h60
M9 Title Sheet:
  drawing of 57 lines, arcs and shapes, not listed
  text "1" at 608.84,8040.52 h70
  text "2" at 3104.5,8040.52 h70
  text "3" at 5593.84,8040.52 h70
  text "4" at 8100.51,8040.52 h70
  text "5" at 10599.5,8040.52 h70
  text "6" at 13104.5,8040.52 h70
  text "A" at -547.5,6897.52 h70
  text "A" at 14252.5,6897.52 h70
  text "B" at -547.5,4517.52 h70
  text "B" at 14252.5,4517.52 h70
  text "C" at -547.5,2142.52 h70
  text "C" at 14252.5,2142.52 h70
  text "PROJECT TITLE:" at 11212.5,281.52 h45
  text ".PRJ_Title" at 11262.5,148.19 h70
  text "DESIGNED FOR:" at 11212.5,-19.48 h45
  text ".PRJ_Customer" at 11262.5,-159.48 h70
  text "D" at -547.5,-227.48 h70
  text "D" at 14252.5,-227.48 h70
  text "FILE NAME:" at 11212.5,-319.48 h45
  text ".PCB_File_Name_No_Path" at 11262.5,-439.48 h70
  text "Texas Instruments (TI) and/or its licensors do not warrant the accuracy or completeness of this specification" at 6243,-601.32 h45
  text "ENGINEER:" at 11212.5,-609.48 h45
  text "LAYOUT BY:" at 12717.5,-609.48 h45
  text "or any information contained therein. TI and/or its licensors do not warrant that this design will meet" at 6198.01,-713.99 h45
  text ".PRJ_Engineer" at 11262.5,-764.48 h70
  text ".PCB_Layout" at 12768,-764.48 h70
  text "the specifications, will be suitable for your application or fit for any particular purpose, or will operate in" at 6198.01,-826.65 h45
  text ".Layer_Name" at 446,-854.48 h60
  text "ALTIUM DESIGNER VERSION:" at 12717.5,-919.48 h45
  text "an implementation. TI and/or its licensors do not warrant that the design is production worthy. You should" at 6198.01,-939.32 h45
  text "completely validate and test your design implementation to confirm the system functionality for your application." at 6243,-1051.98 h45
  text ".print_Scale" at 11262.5,-1052.81 h70
  text ".Application_BuildNumber" at 12768,-1052.81 h70
  text "1" at 608.84,-1259.48 h70
  text "2" at 3104.5,-1259.48 h70
  text "3" at 5593.84,-1259.48 h70
  text "4" at 8100.51,-1259.48 h70
  text "5" at 10599.5,-1259.48 h70
  text "6" at 13104.5,-1259.48 h70
M10 Fab Notes:
  drawing of 484 lines, arcs and shapes, not listed
  text "Layer" at 7317.85,7515.11 h50.84
  text "Name" at 7668.21,7515.11 h50.84
  text "Material" at 8467.47,7515.11 h50.84
  text "Thickness" at 9198.98,7515.11 h50.84
  text "Constant" at 9752.61,7515.11 h50.84
  text "Board Layer Stack" at 10238.49,7515.11 h50.84
  text "Top Overlay" at 7668.21,7413.44 h50.84
  text "Top Solder" at 7668.21,7311.77 h50.84
  text "Solder Resist" at 8467.47,7311.77 h50.84
  text "1.00mil" at 9198.98,7311.77 h50.84
  text "3.4" at 9752.61,7311.77 h50.84
  text "1" at 7317.85,7210.1 h50.84
  text "Top Layer" at 7668.21,7210.1 h50.84
  text "3.00mil" at 9198.98,7210.1 h50.84
  text "Dielectric 1" at 7668.21,7108.43 h50.84
  text "FR-4 High Tg" at 8467.47,7108.43 h50.84
  text "8.10mil" at 9198.98,7108.43 h50.84
  text "4.6" at 9752.61,7108.43 h50.84
  text "2" at 7317.85,7006.75 h50.84
  text "Signal Layer 1" at 7668.21,7006.75 h50.84
  text "1.50mil" at 9198.98,7006.75 h50.84
  text "Dielectric 2" at 7668.21,6905.08 h50.84
  text "FR-4 High Tg" at 8467.47,6905.08 h50.84
  text "34.80mil" at 9198.98,6905.08 h50.84
  text "4.6" at 9752.61,6905.08 h50.84
  text "3" at 7317.85,6803.41 h50.84
  text "Signal Layer 2" at 7668.21,6803.41 h50.84
  text "1.50mil" at 9198.98,6803.41 h50.84
  text "Dielectric 3" at 7668.21,6701.74 h50.84
  text "FR-4 High Tg" at 8467.47,6701.74 h50.84
  text "8.10mil" at 9198.98,6701.74 h50.84
  text "4.6" at 9752.61,6701.74 h50.84
  text "4" at 7317.85,6600.07 h50.84
  text "Bottom Layer" at 7668.21,6600.07 h50.84
  text "3.00mil" at 9198.98,6600.07 h50.84
  text "Bottom Solder" at 7668.21,6498.4 h50.84
  text "Solder Resist" at 8467.47,6498.4 h50.84
  text "1.00mil" at 9198.98,6498.4 h50.84
  text "3.4" at 9752.61,6498.4 h50.84
  text "Bottom Overlay" at 7668.21,6396.72 h50.84
  text "DESIGN INFORMATION" at 12251.02,6360.19 h60
  text "Total board thickness:" at 7317.85,6295.05 h50.84
  text "62.00mil" at 9198.98,6295.05 h50.84
  text "MIN. TRACK WIDTH:" at 11606.46,6228.06 h60
  text "7" at 12702.7,6228.07 h60
  text "MIL" at 12857.46,6228.06 h60
  text "MIN. CLEARANCE:" at 11606.46,6103.94 h60
  text "0.2" at 12642.7,6103.94 h60
  text "mm" at 12857.46,6103.94 h60
  text "17.457" at 12507.87,5988.19 h60
  text "MIN. VIA PAD SIZE:" at 11606.46,5979.81 h60
  text "MIL" at 12857.46,5979.81 h60
  text "0.05mm (2MIL)" at 12301.46,5849.91 h60
  text "MINIMUM ANNULAR RING" at 11277.23,5841.69 h60
  text "EXTERNAL" at 13009.46,5841.69 h60
  text "PER" at 11477.23,5731.56 h60
  text "IPC-D-275 CLASS 2 LEVEL C" at 11697.23,5731.56 h60
  text "MIL, HOLES" at 13185.46,5631.08 h60
  text "+/-" at 12793,5622.5 h60
  text "+/-" at 13647,5622.5 h60
  text "REGISTRATION TOLERANCES:" at 11277.23,5621.43 h60
  text "METAL" at 12477,5621.43 h60
  text "5" at 13053.2,5621.44 h60
  text "3" at 13886.2,5621.44 h60
  text "MIL" at 14002.46,5621.43 h60
  text "HOLE SIZE TOLERANCE (UNLESS OTHERWISE SPECIFIED):" at 11277.23,5523.12 h60
  text "+/-" at 13647,5520.25 h60
  text "3" at 13886.2,5519.18 h60
  text "MIL" at 14002.46,5519.18 h60
  text "MATERIAL:" at 11202.46,5381.53 h60
  text "FR-4 High Tg" at 12188.9,5253.01 h60
  text "X" at 12043.31,5251.97 h60
  text "FR-408" at 11623.46,5240.5 h60
  text "OTHER" at 13111.46,5240.5 h60
  text "X" at 11826.77,5102.36 h60
  text "62 MIL (1.6mm) +/-10%" at 11943.56,5097.47 h60
  text "THICKNESS:" at 11277.23,5089.25 h60
  text "OTHER" at 13228.46,5089.25 h60
  text "TOLERANCE:" at 11277.23,4950.94 h60
  text "X" at 12125.46,4950.94 h60
  text "ANSI IPC-6012 TYPE 3 CLASS 2" at 12303.48,4950.94 h60
  text "OTHER +/-" at 12303.46,4806.75 h60
  text "BOW & TWIST:" at 11277.23,4661.56 h60
  text "X" at 12125.46,4661.56 h60
  text "ANSI IPC-6012 TYPE 3 CLASS 2" at 12303.48,4661.56 h60
  text "OTHER +/-" at 12303.46,4514.86 h60
  text "DRILLING:" at 11202.46,4384.24 h60
  text "NC_DRILL FILES" at 12963.46,4279.06 h60
  text "REFERENCE:" at 11277.23,4275.12 h60
  text "X" at 11934.46,4275.02 h60
  text "AS SHOWN" at 12112.46,4275.12 h60
  text "X" at 12835.46,4275.12 h60
  text "OTHER" at 13261.46,4132.87 h60
  text "PTH COPPER THICKNESS:" at 11276.91,4129.34 h60
  text "X" at 12416.14,4129.34 h60
  text "20-30 um" at 12544.14,4129.34 h60
  text "BOARD FINISH:" at 11202.46,3981.74 h60
  text "SILKSCREEN:" at 11357.68,3871.61 h60
  text "X" at 12315.46,3871.61 h60
  text "TOP" at 12432.46,3871.61 h60
  text "X" at 12825.46,3871.61 h60
  text "BOTTOM" at 12943.46,3871.61 h60
  text "SILKSCREEN COLOR:" at 11357.68,3716.43 h60
  text "X" at 12314.46,3716.43 h60
  text "WHITE" at 12432.46,3716.43 h60
  text "OTHER" at 12943.46,3716.43 h60
  text "RED" at 13704.72,3586.61 h51.18
  text "GREEN" at 12563.46,3572.98 h60
  text "X" at 13031.46,3572.98 h60
  text "OTHER" at 13181.46,3572.98 h60
  text "SOLDER RESIST COLOR:" at 11357.68,3566.11 h60
  text "X" at 12445.46,3418.73 h60
  text "MATTE" at 12563.46,3418.73 h60
  text "SEMI-GLOSS" at 13181,3418.09 h60
  text "IMMERSION GOLD (ENIG)" at 12263.46,3245.95 h60
  text "ENEPIG" at 13601,3238.73 h60
  text "SURFACE FINISH:" at 11202.46,3237.73 h60
  text "X" at 12085.46,3237.73 h60
  text "IMM. TIN/SILVER OR EQUIV" at 11532,3100.42 h60
  text "OTHER" at 12963.46,3096.48 h60
  text "ARRAY/PANEL:" at 11202.46,2941.1 h60
  text "CUT AND TRIM PER M1 BOARD OUTLINE" at 12263.46,2932.88 h60
  text "N.C. ROUTE" at 12263.46,2796.91 h60
  text "X" at 12951.46,2796.91 h60
  text "V. SCORE" at 13129.46,2796.91 h60
  text "CERTIFICATION:" at 11202.46,2667.79 h60
  text "MATERIALS AND WORKMANSHIP FOR ALL PCBS" at 11927.46,2667.79 h60
  text "TO MEET OR EXCEED THE REQUIREMENTS OF:" at 11927.46,2573.72 h60
  text "X" at 11564.97,2445.1 h60
  text "ANSI IPC-A-600F CLASS ->" at 11692.96,2445.1 h60
  text "X" at 13340.97,2445.1 h60
  text "2" at 13450.96,2445.1 h60
  text "1" at 13135.96,2443.6 h60
  text "3" at 13804.96,2443.6 h60
  text "X" at 12376.97,2297.41 h60
  text "RoHS" at 12504.96,2297.41 h60
  text "OTHER" at 13149.36,2297.41 h60
  text "PER ORDER" at 13546.42,2297.41 h60
  text "ALL BOARDS MUST MEET OR EXCEED UL94-V0 REQUIREMENTS." at 11230,2143.58 h60
  text "PCB MUST BEAR THE UL94V-0 UL REGISTERED MATERIAL ID NUMBER" at 11230,2027.52 h60
  text "ADDITIONAL REQUIREMENTS:" at 11202.46,1858.09 h60
  text "MICROSECTION:" at 11277.23,1750.97 h60
  text "YES" at 12182.96,1750.97 h60
  text "REQUIRED" at 13044.46,1606.64 h60
  text "BARE BOARD ELEC. TEST:" at 11277.23,1603.78 h60
  text "NONE" at 12582.96,1603.78 h60
  text "X" at 12926.46,1603.78 h60
  text "PER ORDER" at 13636.46,1603.78 h60
  text "XX MIL VIAS REQUIRE NON-CONDUCTIVE FILL AND PLANARIZE" at 11445.38,1398.83 h59
  text "XX MIL VIAS REQUIRE CONDUCTIVE FILL AND PLANARIZE" at 11453.38,1294.86 h60
  text "OUTER XX MIL TRACES REQUIRE 50 OHM SINGLE-ENDED IMPEDANCE" at 11452.39,1131.47 h58
  text "LAYER 2 & 3 (INNER LAYERS) XX MIL WIDE, XX MIL SPACE / TRACES REQUIRE 100 OHM DIFFERENTIAL IMPEDANCE" at 11444.39,895.76 h60
  text ".Layer_Name" at 446,-854.48 h60
M11 Gerber Information:
  lines w10: -423,-926.15 6177,-926.15 ; -423,-722.82 6179,-722.82 ; -423,-519.48 -423,-1129.48 3582,-1129.48 6179,-1129.48 6179,-519.48 -422.5,-519.48 -422.5,-1129.48 1153,-1129.48 ; 2042,-1129.48 2042,-519.48 ; 3309,-722.82 3309,-519.48 ; 4149,-722.82 4149,-519.48 ; 4771,-1135.98 4771,-933.15
  text "ALL ARTWORK VIEWED FROM TOP SIDE" at -359.5,-651.65 h60
  text "BOARD #:" at 2117,-651.65 h60
  text ".PRJ_Number" at 2662.5,-651.65 h60
  text "REV:" at 3507,-651.65 h60
  text ".PCB_Rev" at 3798.5,-651.65 h60
  text "SVN REV:" at 4345,-651.65 h60
  text ".VersionControl_RevNumber" at 4851,-651.65 h60
  text "LAYER NAME =" at -359.5,-854.48 h60
  text "TID #:" at 2117,-854.98 h60
  text ".TID" at 2662.5,-854.98 h60
  text "PLOT NAME =" at -359.5,-1060.32 h60
  text ".plot_File_Name" at 446,-1060.32 h60
  text "GENERATED    :" at 2119,-1060.32 h60
  text ".Print_Date" at 2988.5,-1060.32 h60
  text ".Print_Time" at 3717.5,-1060.32 h60
  text "TEXAS INSTRUMENTS" at 4982,-1060.32 h60
M12 Stackup:
  text ".Layer_Name" at 446,-854.48 h60
M13 Component Bodies Top:
  text ".Layer_Name" at 446,-854.48 h60
M14 Component Bodies Bottom:
  text ".Layer_Name" at 446,-854.48 h60
M15 Courtyards Top:
  text ".Layer_Name" at 446,-854.48 h60
M16 Courtyards Bottom:
  text ".Layer_Name" at 446,-854.48 h60
Drill Drawing:
  drawing of 184 lines, arcs and shapes, not listed
  text "Symbol" at 4127.4,4919.15 h72
  text "Count" at 4427.97,4919.15 h72
  text "Hole Size" at 4757.25,4919.15 h72
  text "Plated" at 5347.16,4919.15 h72
  text "Hole Type" at 5606.3,4919.15 h72
  text "Drill Layer Pair" at 5981.46,4919.15 h72
  text "Hole Tolerance" at 6705.79,4919.15 h72
  text "27" at 4427.97,4794.83 h60
  text "7.87mil (0.200mm)" at 4757.25,4794.83 h60
  text "PTH" at 5347.16,4794.83 h60
  text "Round" at 5606.3,4794.83 h60
  text "Top Layer - Bottom Layer" at 5981.46,4794.83 h60
  text "12" at 4427.97,4670.51 h60
  text "8.00mil (0.203mm)" at 4757.25,4670.51 h60
  text "PTH" at 5347.16,4670.51 h60
  text "Round" at 5606.3,4670.51 h60
  text "Top Layer - Bottom Layer" at 5981.46,4670.51 h60
  text "7" at 4427.97,4546.19 h60
  text "10.00mil (0.254mm)" at 4757.25,4546.19 h60
  text "PTH" at 5347.16,4546.19 h60
  text "Round" at 5606.3,4546.19 h60
  text "Top Layer - Bottom Layer" at 5981.46,4546.19 h60
  text "890" at 4427.97,4421.87 h60
  text "12.00mil (0.305mm)" at 4757.25,4421.87 h60
  text "PTH" at 5347.16,4421.87 h60
  text "Round" at 5606.3,4421.87 h60
  text "Top Layer - Bottom Layer" at 5981.46,4421.87 h60
  text "402" at 4427.97,4297.55 h60
  text "12.01mil (0.305mm)" at 4757.25,4297.55 h60
  text "PTH" at 5347.16,4297.55 h60
  text "Round" at 5606.3,4297.55 h60
  text "Top Layer - Bottom Layer" at 5981.46,4297.55 h60
  text "A" at 4102.11,4287.56 h55.25
  text "6" at 4427.97,4173.23 h60
  text "12.99mil (0.330mm)" at 4757.25,4173.23 h60
  text "PTH" at 5347.16,4173.23 h60
  text "Round" at 5606.3,4173.23 h60
  text "Top Layer - Bottom Layer" at 5981.46,4173.23 h60
  text "42" at 4427.97,4048.91 h60
  text "27.56mil (0.700mm)" at 4757.25,4048.91 h60
  text "PTH" at 5347.16,4048.91 h60
  text "Round" at 5606.3,4048.91 h60
  text "Top Layer - Bottom Layer" at 5981.46,4048.91 h60
  text "51" at 4427.97,3924.59 h60
  text "40.00mil (1.016mm)" at 4757.25,3924.59 h60
  text "PTH" at 5347.16,3924.59 h60
  text "Round" at 5606.3,3924.59 h60
  text "Top Layer - Bottom Layer" at 5981.46,3924.59 h60
  text "8" at 4427.97,3800.27 h60
  text "42.91mil (1.090mm)" at 4757.25,3800.27 h60
  text "PTH" at 5347.16,3800.27 h60
  text "Round" at 5606.3,3800.27 h60
  text "Top Layer - Bottom Layer" at 5981.46,3800.27 h60
  text "4" at 4427.97,3675.95 h60
  text "59.06mil (1.500mm)" at 4757.25,3675.95 h60
  text "PTH" at 5347.16,3675.95 h60
  text "Round" at 5606.3,3675.95 h60
  text "Top Layer - Bottom Layer" at 5981.46,3675.95 h60
  text "+/-5.12mil" at 6705.79,3675.95 h60
  text "6" at 4427.97,3551.63 h60
  text "62.99mil (1.600mm)" at 4757.25,3551.63 h60
  text "NPTH" at 5347.16,3551.63 h60
  text "Round" at 5606.3,3551.63 h60
  text "Top Layer - Bottom Layer" at 5981.46,3551.63 h60
  text "6" at 4427.97,3427.31 h60
  text "63.00mil (1.600mm)" at 4757.25,3427.31 h60
  text "PTH" at 5347.16,3427.31 h60
  text "Round" at 5606.3,3427.31 h60
  text "Top Layer - Bottom Layer" at 5981.46,3427.31 h60
  text "2" at 4427.97,3302.99 h60
  text "66.93mil (1.700mm)" at 4757.25,3302.99 h60
  text "PTH" at 5347.16,3302.99 h60
  text "Round" at 5606.3,3302.99 h60
  text "Top Layer - Bottom Layer" at 5981.46,3302.99 h60
  text "3" at 4427.97,3178.67 h60
  text "98.43mil (2.500mm)" at 4757.25,3178.67 h60
  text "PTH" at 5347.16,3178.67 h60
  text "Round" at 5606.3,3178.67 h60
  text "Top Layer - Bottom Layer" at 5981.46,3178.67 h60
  text "4" at 4427.97,3054.35 h60
  text "125.98mil (3.200mm)" at 4757.25,3054.35 h60
  text "PTH" at 5347.16,3054.35 h60
  text "Round" at 5606.3,3054.35 h60
  text "Top Layer - Bottom Layer" at 5981.46,3054.35 h60
  text "4" at 4427.97,2930.03 h60
  text "133.86mil (3.400mm)" at 4757.25,2930.03 h60
  text "NPTH" at 5347.16,2930.03 h60
  text "Round" at 5606.3,2930.03 h60
  text "Top Layer - Bottom Layer" at 5981.46,2930.03 h60
  text "1474 Total" at 4427.97,2805.71 h60
  text ".Layer_Name" at 446,-854.48 h60
M17 Embedded Cavity:
  text ".Layer_Name" at 446,-854.48 h60
M18 Embedded Assembly:
  text ".Layer_Name" at 446,-854.48 h60
M19 Embedded Keepout:
  text ".Layer_Name" at 446,-854.48 h60

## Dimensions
-131,-395.98 to 869,-395.98 on M2 Board Dimensions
